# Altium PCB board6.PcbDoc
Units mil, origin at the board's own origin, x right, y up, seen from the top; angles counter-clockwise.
Board outline 1968.5 x 1181.1 mil, 6 copper layers (Top Layer, Mid-Layer 1, Internal Plane 1, Mid-Layer 3, Mid-Layer 4, Bottom Layer), stack 61.418 mil thick; 4 components, 4 nets, 15 pads, 3 vias.
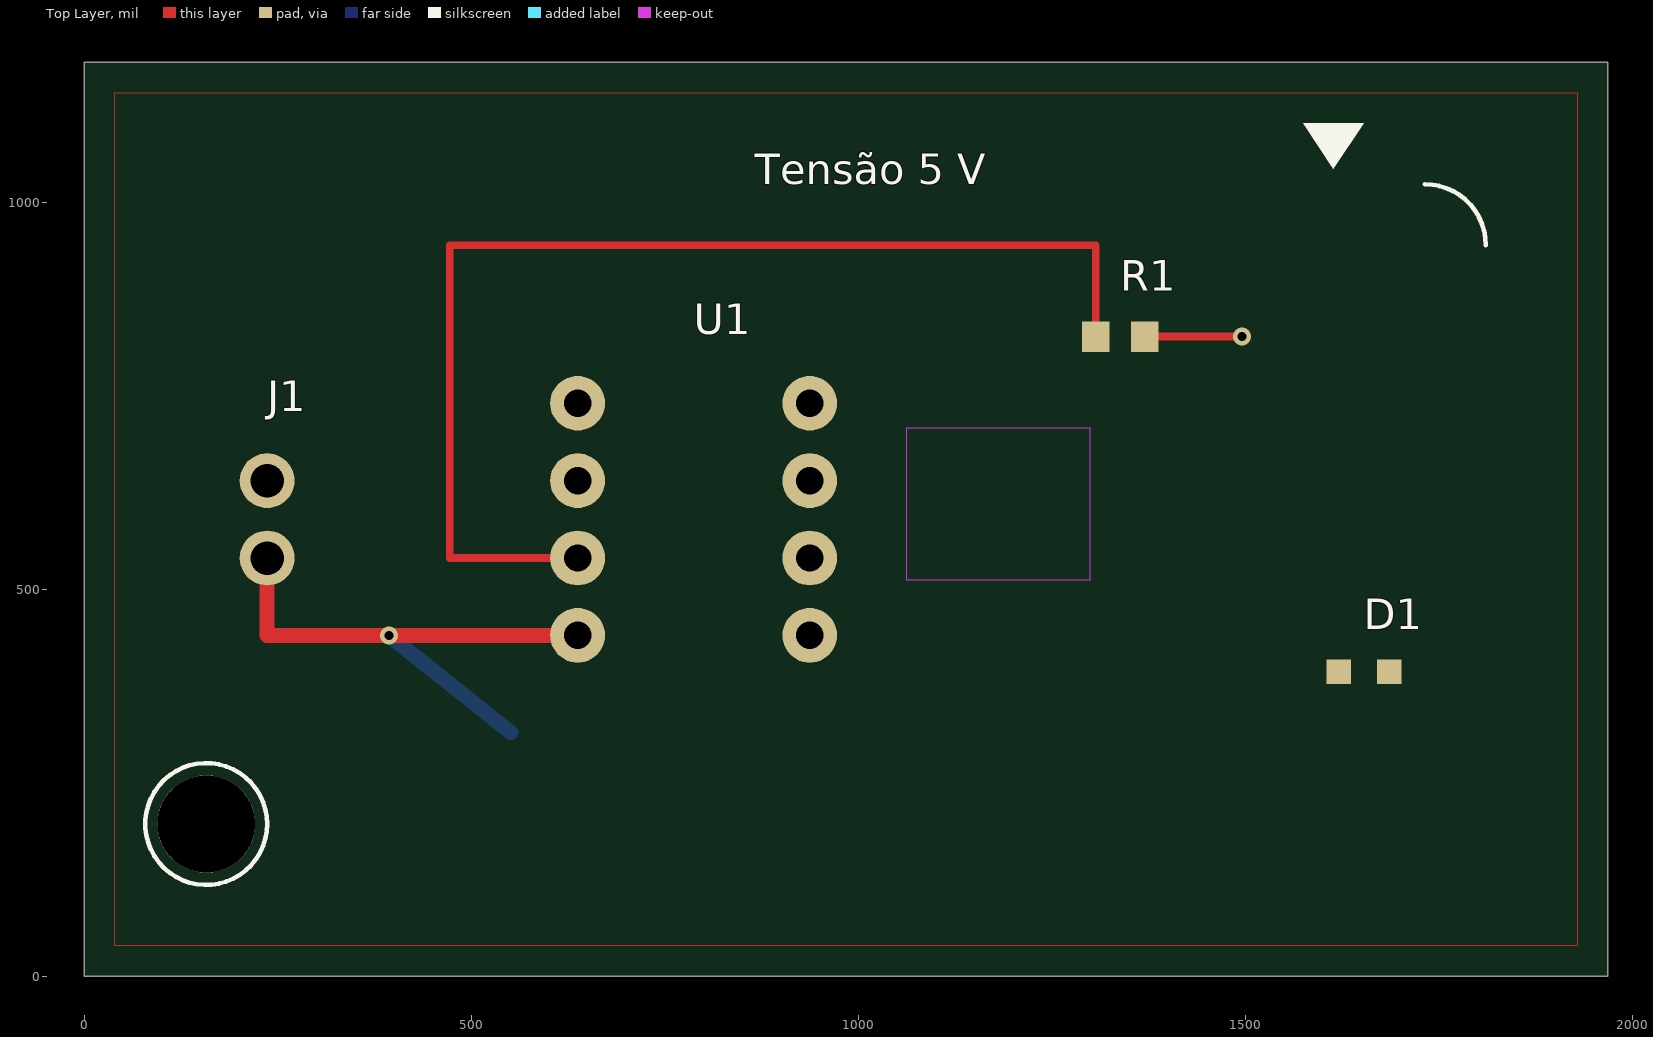
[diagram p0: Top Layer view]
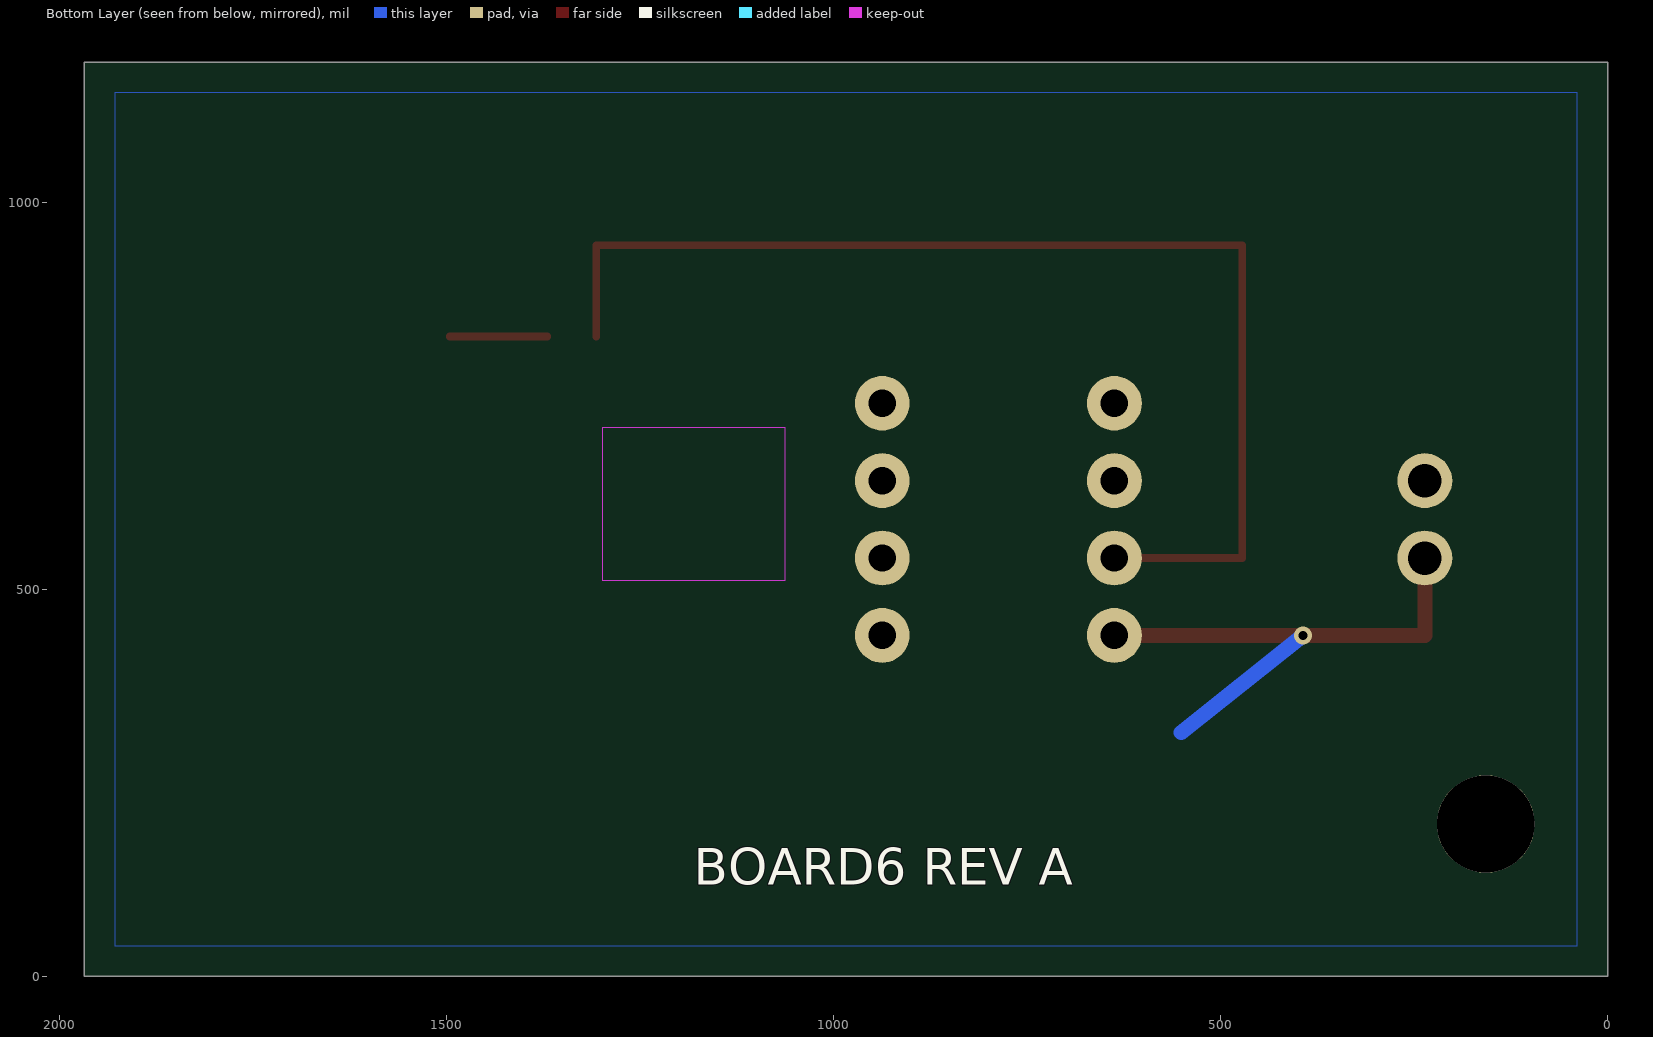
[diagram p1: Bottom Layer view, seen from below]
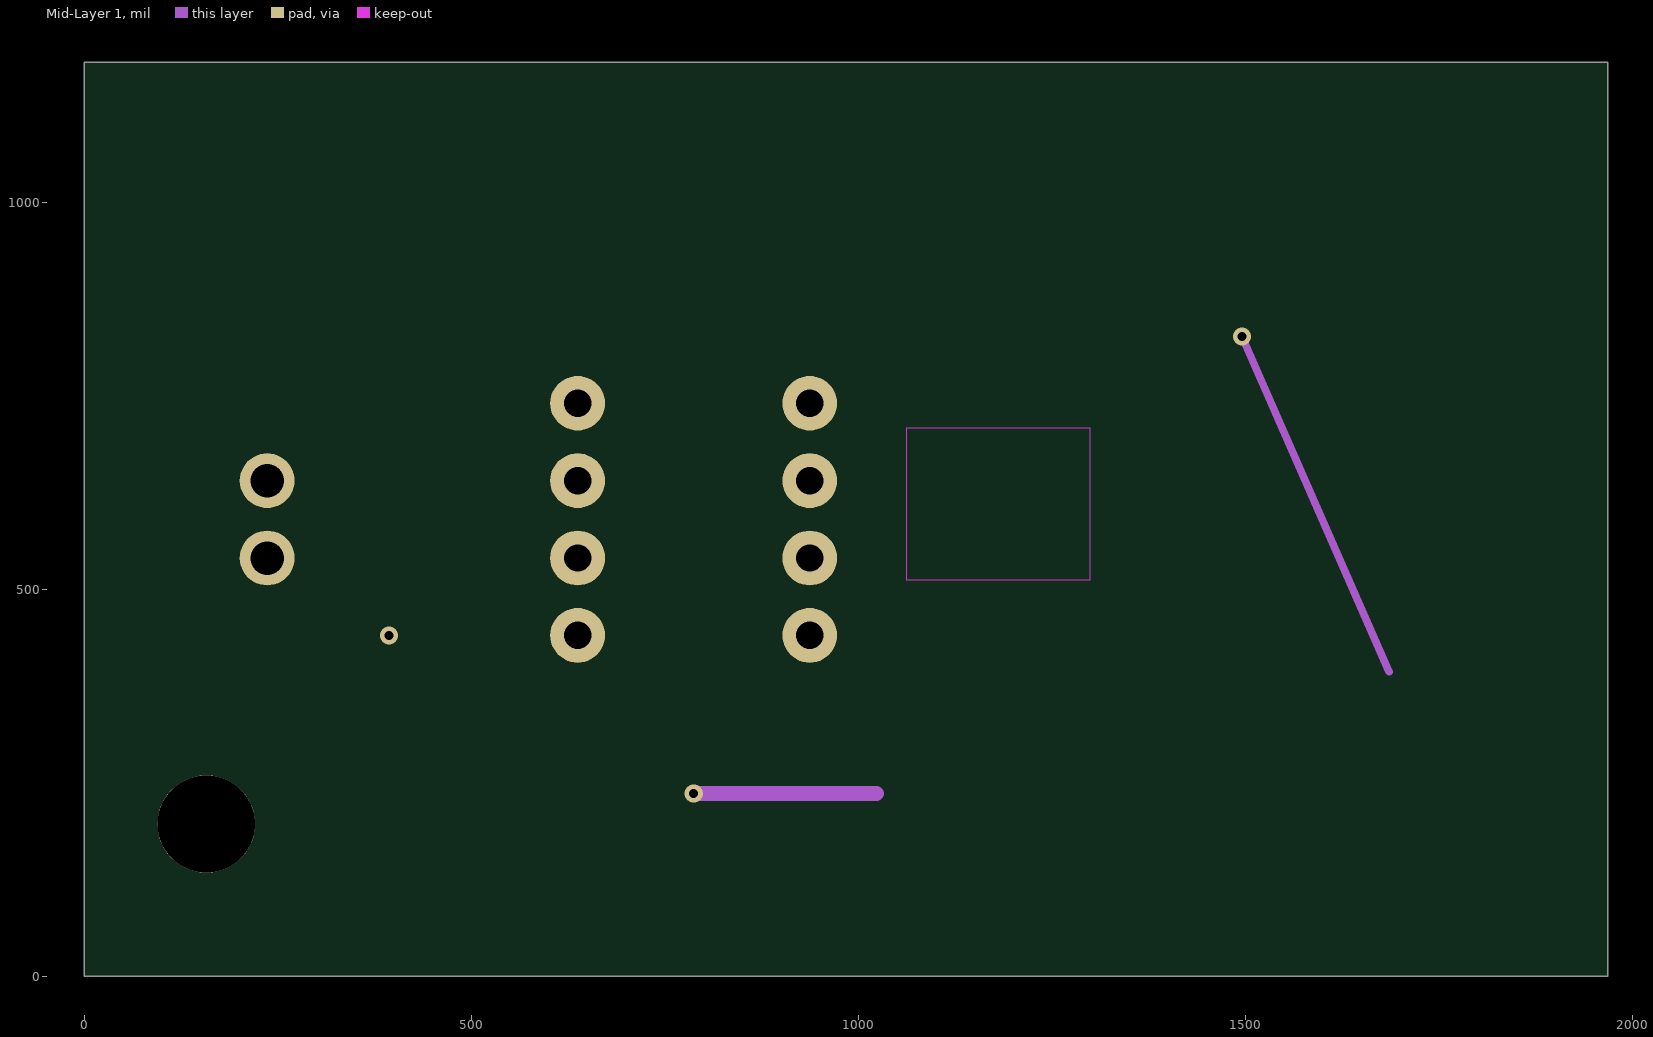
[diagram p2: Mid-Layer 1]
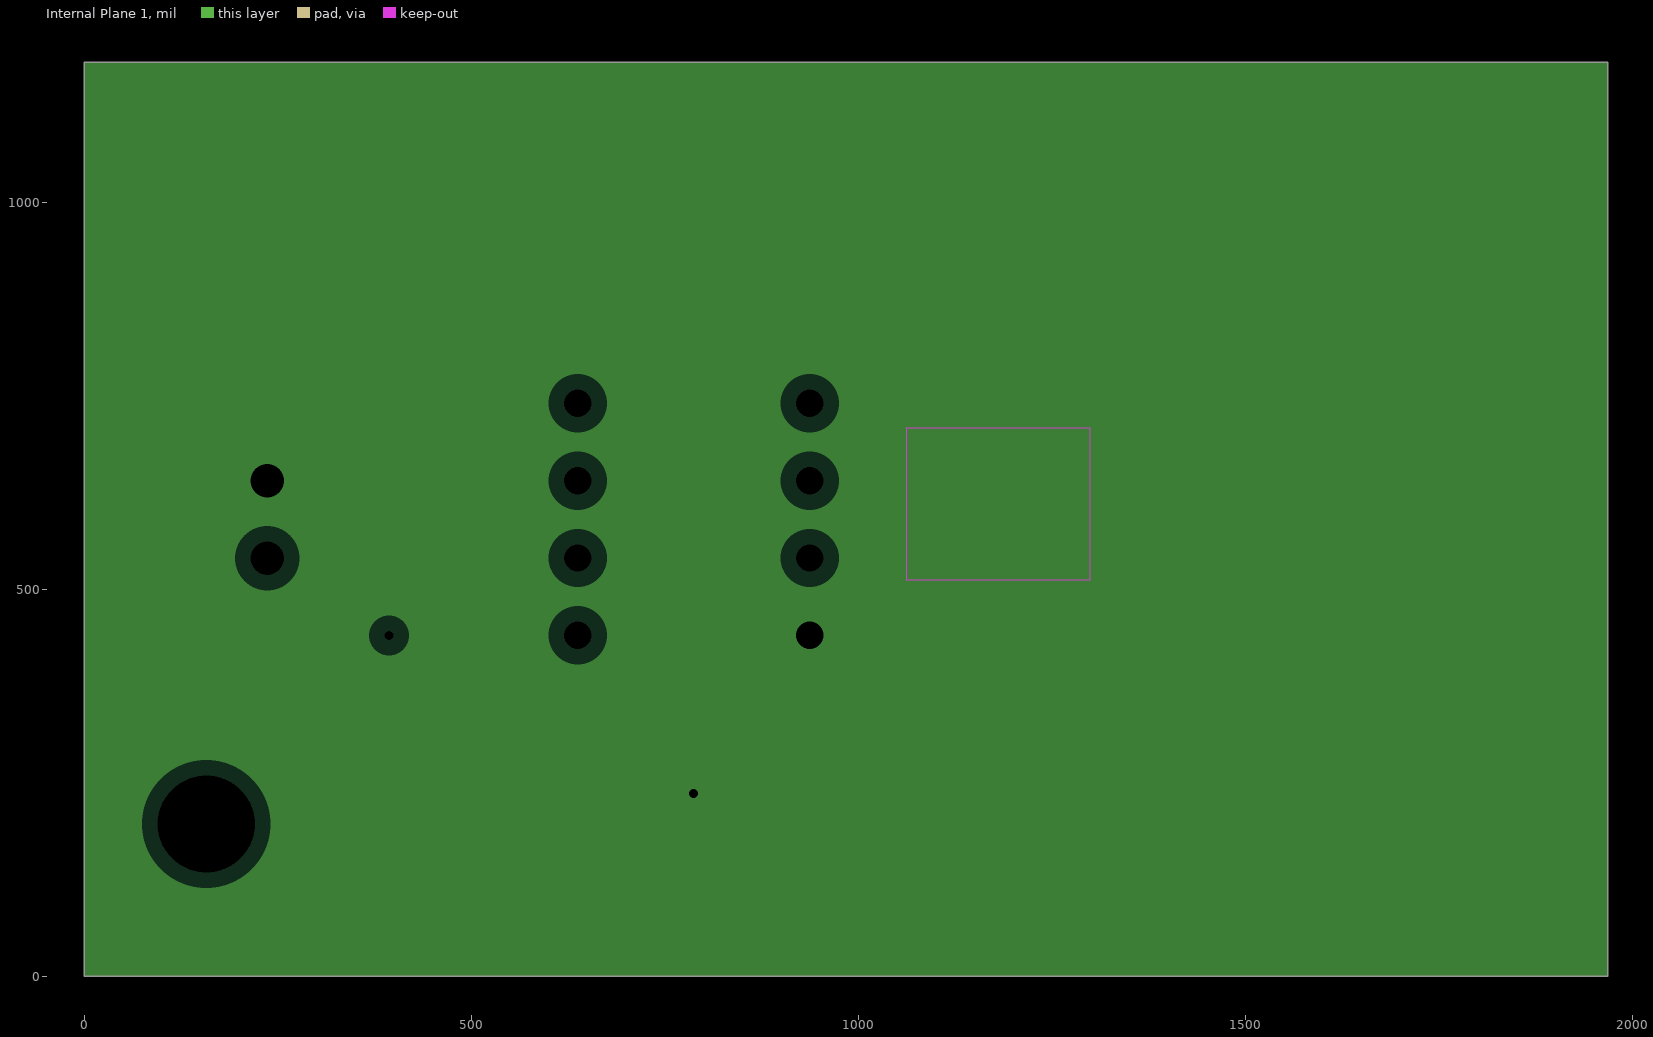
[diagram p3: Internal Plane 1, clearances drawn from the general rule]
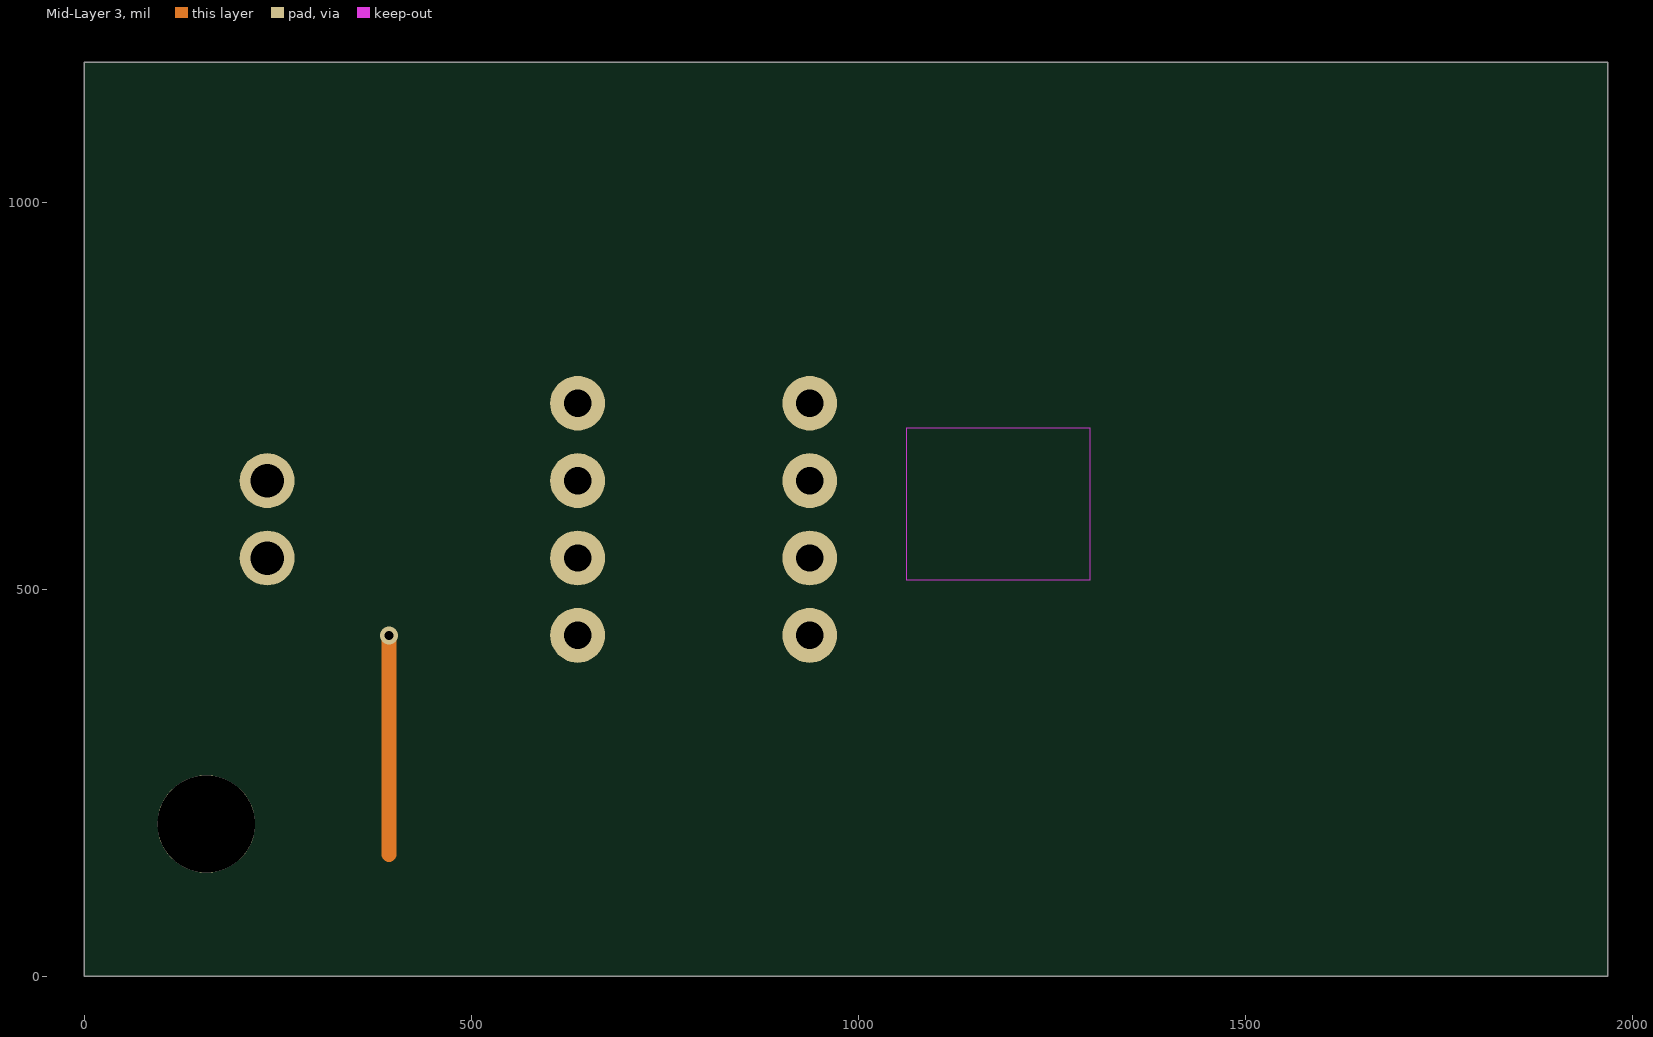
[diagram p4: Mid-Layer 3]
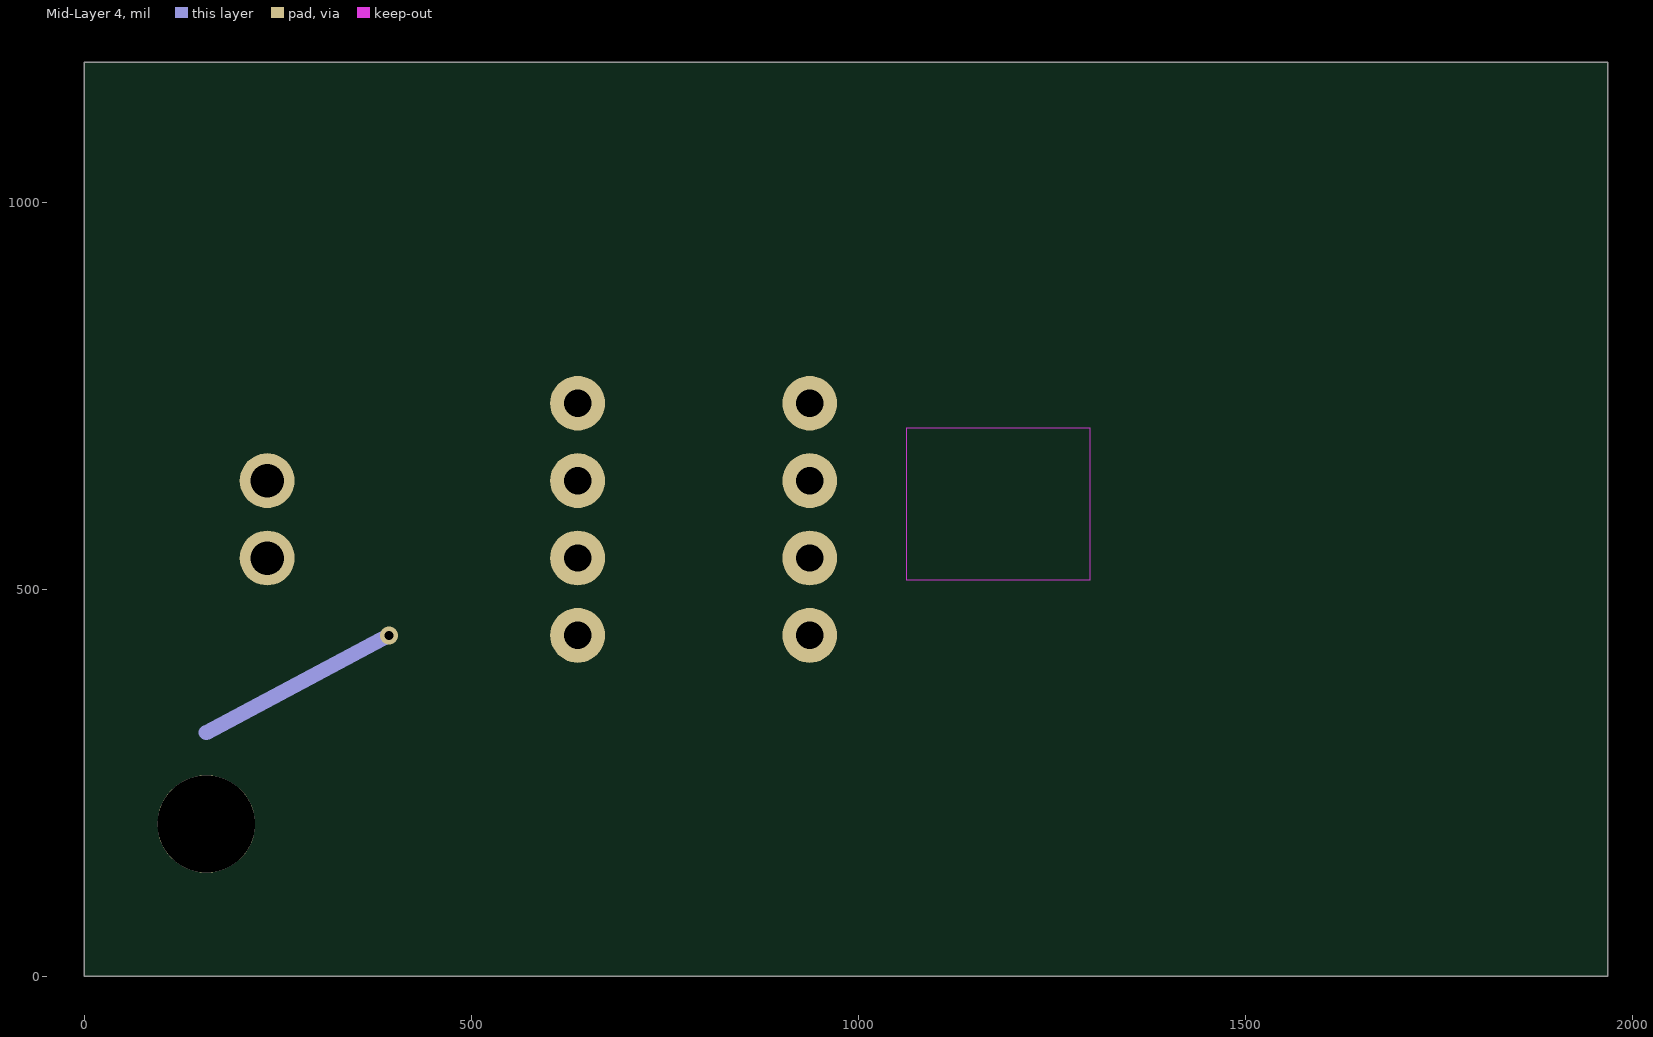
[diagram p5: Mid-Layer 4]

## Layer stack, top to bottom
Top Solder: solder mask 0.4, Solder Resist, Dk 3.5
Top Layer: signal copper 1.378
Dielectric 1: prepreg 4.3307, FR-4 prepreg, Dk 4.2
Mid-Layer 1: signal copper 0.689
Dielectric 2: core 7.874, FR-4 core, Dk 4.5
Internal Plane 1: plane copper 0.689, net GND
Dielectric 3: prepreg 31.4961, FR-4 prepreg, Dk 4.2
Mid-Layer 3: signal copper 0.689
Dielectric 4: core 7.874, FR-4 core, Dk 4.5
Mid-Layer 4: signal copper 0.689
Dielectric 5: prepreg 4.3307, FR-4 prepreg, Dk 4.2
Bottom Layer: signal copper 1.378
Bottom Solder: solder mask 0.4, Solder Resist, Dk 3.5

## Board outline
0,1181.1 1968.5,1181.1 1968.5,0 0,0

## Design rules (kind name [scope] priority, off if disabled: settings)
Clearance Clearance_PWR [InNetClass('PWR')] p1: gap=7.87 ignorepadtopadclearanceinfootprint=FALSE
Clearance [All] p2: gap=7.87 ignorepadtopadclearanceinfootprint=FALSE
RoutingVias [All] p1: holewidth=11.81 width=23.62 viastyle="Through Hole" minholewidth=11.81 minwidth=23.62 maxholewidth=11.81 maxwidth=23.62
Width Width_PWR [InNetClass('PWR')] p1: maxlimit=19.68 minlimit=19.68 preferedwidth=19.68
Width [All] p2: maxlimit=19.68 minlimit=9.84 preferedwidth=9.84

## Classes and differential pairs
net class PWR: GND VIN

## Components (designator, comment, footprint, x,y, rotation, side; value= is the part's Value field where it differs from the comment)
D1 "red" LED0603_Kingbright_APT1608SURCK 1653.54,393.7 r0 top
J1 "SUPPLY" Header_1x2_P2.54 236.22,590.55 r0 top
R1 "330" Chip_0603 1338.58,826.77 r0 top
U1 "MCU" DIP8_Microchip_P 787.4,590.55 r0 top locked

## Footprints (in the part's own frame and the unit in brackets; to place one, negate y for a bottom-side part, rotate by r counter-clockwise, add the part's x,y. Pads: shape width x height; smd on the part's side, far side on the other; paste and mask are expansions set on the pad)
Chip_0603 [mm]
  rect 0.9x1 smd: 1(-0.8,0) 2(0.8,0)
DIP8_Microchip_P [mm]
  round 1.8 hole 0.9: 1(-3.81,-3.81) 2(-3.81,-1.27) 3(-3.81,1.27) 4(-3.81,3.81) 5(3.81,3.81) 6(3.81,1.27) 7(3.81,-1.27) 8(3.81,-3.81)
Header_1x2_P2.54 [mm]
  round 1.8 hole 1.1: 1(0,-1.27) 2(0,1.27)
LED0603_Kingbright_APT1608SURCK [mm]
  rect 0.8x0.8 smd: 1(-0.825,0) 2(0.825,0)

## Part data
D1: library part LED
J1: library part Connector_2
R1: library part Resistor
U1: library part Microcontroller

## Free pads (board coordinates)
  round 125.98 hole 125.98 unplated: ""(157.48,196.85)

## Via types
v1: diameter 23.62, hole 11.81, Mid-Layer 1 to Internal Plane 1, 1 vias
v2: diameter 23.62, hole 11.81, Top Layer to Mid-Layer 1, 1 vias
v3: diameter 23.62, hole 11.81, Top Layer to Bottom Layer, 1 vias

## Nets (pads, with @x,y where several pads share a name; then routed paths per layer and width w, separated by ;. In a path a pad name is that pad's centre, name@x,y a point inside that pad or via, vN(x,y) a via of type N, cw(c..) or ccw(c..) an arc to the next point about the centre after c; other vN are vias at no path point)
GND: D1.1 J1.2 U1.8 | length 236.2
  Mid-Layer 1 w19.68: v1(787.4,236.22) 1023.62,236.22
LED_A: D1.2 R1.2 | length 598.9
  Top Layer w9.84: R1.2 v2(1496.06,826.77)
  Mid-Layer 1 w9.84: v2(1496.06,826.77) 1686.02,393.7
LED_DRV: R1.1 U1.2 | length 1522
  Top Layer w9.84: U1.2 472.44,540.55 472.44,944.88 1307.09,944.88 R1.1
VIN: J1.1 U1.1 | length 1253.2
  Top Layer w19.68: J1.1 236.22,440.55 U1.1
  Mid-Layer 3 w19.68: 393.7,157.48 v3(393.7,440.55)
  Mid-Layer 4 w19.68: 157.48,314.96 v3(393.7,440.55)
  Bottom Layer w19.68: v3(393.7,440.55) 551.18,314.96
pads on no net: U1.3 U1.4 U1.5 U1.6 U1.7

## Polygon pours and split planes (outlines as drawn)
GND on Top Layer "GND_L01_P000" (solid, remove dead copper, pour order 0): 39.37,1141.73 1929.13,1141.73 1929.13,39.37 39.37,39.37
GND on Bottom Layer "GND_L06_P001" (solid, remove dead copper, pour order 1): 39.37,1141.73 1929.13,1141.73 1929.13,39.37 39.37,39.37

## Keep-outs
Keep-Out Layer:
  region: 1062.99,708.66 1299.21,708.66 1299.21,511.81 1062.99,511.81

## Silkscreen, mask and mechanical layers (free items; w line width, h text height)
Top Overlay:
  circle w5.91: c157.48,196.85 r78.74
  region: 1574.8,1102.36 1653.54,1102.36 1614.17,1043.31
  lines w5.91: 1732.28,1023.62 cw(c1732.28,944.88) 1811.02,944.88
  text "Tensão 5 V" at 866.14,1023.62 h39.37
Bottom Overlay:
  text "BOARD6 REV A" at 1181.1,118.11 h47.24
Mechanical 13:
  lines w3.94: 78.74,1102.36 472.44,1102.36
  text "ASSEMBLY TOP" at 118.11,78.74 h31.5
Mechanical 14:
  lines w3.94: 1417.32,118.11 1732.28,118.11 1732.28,314.96 1417.32,314.96 1417.32,118.11
  text "BOTTOM" at 1850.39,708.66 h39.37 r90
